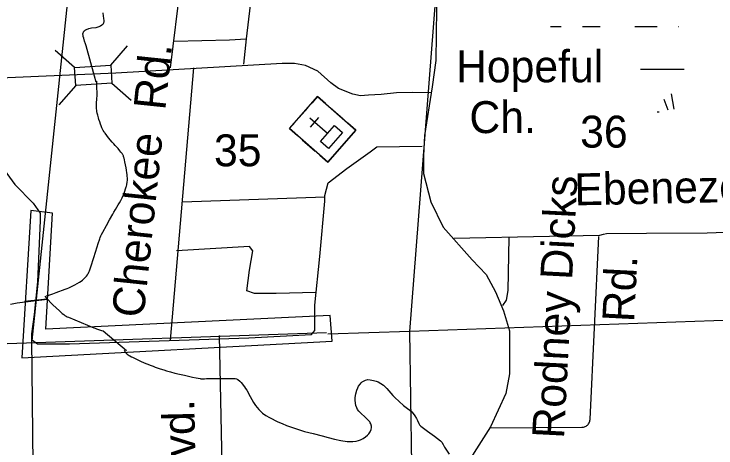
# Model space of a CAD drawing. Extents: x 2480962 to 2688785, y 277103 to 599240.
# Drawn here: x 2571170 to 2581065, y 400443 to 406560 of the extents above; entities that cross this region are included whole.
import ezdxf

# ---------------------------------------------------------------- set-up
doc = ezdxf.new("R2010")
doc.units = 0
for name, color, linetype in [('County Routes Highway Center Lines', 7, 'Continuous'), ('Culture', 7, 'Continuous'), ('Culture Text', 7, 'Continuous'), ('Level 31', 7, 'Continuous'), ('Local Roads Improved', 7, 'Continuous'), ('Local Roads Paved', 7, 'Continuous'), ('Local Roads Related Text', 7, 'Continuous'), ('Narrow River Creek and Branch and Slough', 7, 'Continuous'), ('Section Lines', 7, 'Continuous'), ('Section Numbers', 7, 'Continuous'), ('Swamps', 7, 'Continuous'), ('Township and Range lines', 7, 'Continuous'), ('Uninventoried Roads and Features', 7, 'Continuous')]:
    doc.layers.add(name, color=color, linetype=linetype)

msp = doc.modelspace()

# ---------------------------------------------------------------- linework, layer by layer
at = {"layer": 'County Routes Highway Center Lines'}
msp.add_lwpolyline([(2576923.812, 414892.369), (2576993.261, 413051.984), (2577140.839, 409527.474), (2577158.201, 408260.039), (2577132.158, 407009.966), (2577114.796, 405907.471), (2577062.709, 405534.186), (2576958.537, 404848.382), (2576941.175, 404561.907), (2576941.175, 404310.156), (2577045.347, 403910.828), (2577218.968, 403554.904), (2577626.978, 403094.808), (2577826.643, 402886.463), (2577956.859, 402643.393), (2578069.712, 402374.28), (2578156.523, 402096.486), (2578156.523, 401888.141), (2578156.523, 401488.812), (2578104.437, 401211.018), (2577887.41, 400742.241), (2577435.995, 400030.394)], dxfattribs=at)
at = {"layer": 'Culture'}
for p, q in [((2575447.967, 405396.199), (2575368.975, 405305.864)), ((2575560.884, 405297.46), (2575447.967, 405396.199)), ((2575191.244, 405102.612), (2575309.732, 405238.114)), ((2575809.304, 405080.233), (2575628.635, 405238.216)), ((2575132, 405034.861), (2575053.009, 404944.527)), ((2575589.241, 404874.145), (2575341.166, 405091.071)), ((2575349.329, 404964.377), (2575467.816, 405099.879)), ((2575053.009, 404944.527), (2575165.926, 404845.788)), ((2575989.973, 404922.249), (2575877.055, 405020.989)), ((2575595.015, 404470.577), (2575989.973, 404922.249)), ((2575233.677, 404786.544), (2575414.346, 404628.561)), ((2575482.097, 404569.317), (2575595.015, 404470.577))]:
    msp.add_line(p, q, dxfattribs=at)
for points in [[(2575053.009, 404944.527), (2575447.967, 405396.199), (2575989.973, 404922.249), (2575595.015, 404470.577)], [(2575490.502, 404761.227), (2575687.981, 404987.063), (2575800.899, 404888.323), (2575603.42, 404662.487)]]:
    msp.add_lwpolyline(points, close=True, dxfattribs=at)
at = {"layer": 'Level 31'}
msp.add_lwpolyline([(2571404.517, 403792.853), (2571278.389, 401715.066), (2575653.028, 401947.407), (2575626.475, 402312.513), (2571616.943, 402120.002), (2571709.879, 403753.024)], close=True, dxfattribs=at)
at = {"layer": 'Local Roads Improved'}
for p, q in [((2572532.173, 405841.744), (2572770.214, 406114.523)), ((2572021.353, 405807.006), (2571748.574, 406045.047)), ((2572038.722, 405551.596), (2571800.681, 405278.817)), ((2572549.542, 405586.334), (2572822.321, 405348.293)), ((2579291.39, 400847.78), (2579414.903, 403425.185)), ((2577883.194, 400725.323), (2579174.318, 400734.369))]:
    msp.add_line(p, q, dxfattribs=at)
msp.add_lwpolyline([(2572021.353, 405807.006), (2572532.173, 405841.744), (2572549.542, 405586.334), (2572038.722, 405551.596)], close=True, dxfattribs=at)
for points in [[(2578145.992, 403410.98), (2578129.875, 402661.566), (2578105.701, 402524.576), (2578057.351, 402452.052)], [(2579174.318, 400734.369), (2579186.757, 400735.22), (2579199.038, 400737.368), (2579211.028, 400740.787), (2579222.595, 400745.44), (2579233.612, 400751.278), (2579243.958, 400758.235), (2579253.521, 400766.235), (2579262.195, 400775.192), (2579269.884, 400785.005), (2579276.507, 400795.569), (2579281.989, 400806.768), (2579286.27, 400818.477), (2579289.304, 400830.57), (2579291.057, 400842.914), (2579291.39, 400847.78)]]:
    msp.add_lwpolyline(points, dxfattribs=at)
at = {"layer": 'Local Roads Paved'}
for p, q in [((2573376.092, 401960.683), (2573703.382, 405803.546)), ((2575552.558, 403979.058), (2573544.335, 403908.18)), ((2574061.238, 402028.818), (2574175.504, 396746.483))]:
    msp.add_line(p, q, dxfattribs=at)
for points in [[(2574502.702, 408403.069), (2574523.47, 408119.878), (2574523.47, 407330.09), (2574497.144, 406685.096), (2574444.491, 406211.223), (2574405.002, 405855.818)], [(2573374.423, 405800.724), (2573520.709, 406991.392), (2573578.527, 407488.13), (2573602.05, 407685.495), (2573681.029, 407830.289), (2573996.945, 408027.736), (2574286.534, 408185.694), (2574520.003, 408183.922)], [(2573426.204, 406176.29), (2574207.555, 406198.06), (2574444.491, 406211.223)], [(2577052.818, 405449.786), (2576781.118, 405455.692), (2576562.576, 405449.786), (2576344.034, 405426.16), (2576166.838, 405414.347), (2576054.613, 405408.44), (2575948.296, 405432.066), (2575741.567, 405508.851), (2575635.249, 405591.543), (2575452.147, 405756.926), (2575280.857, 405833.711), (2575121.381, 405863.243), (2574950.091, 405863.243), (2572605.196, 405727.393), (2570750.543, 405644.702), (2570431.59, 405632.888), (2570257.03, 405632.888)], [(2570992.711, 404416.142), (2571181.72, 404156.254), (2571441.608, 403896.366), (2571536.112, 403754.61), (2571536.112, 403648.292), (2571500.673, 402785.937), (2571453.421, 402325.228), (2571417.982, 402053.527), (2571417.982, 401970.835), (2571500.673, 401911.77), (2571949.57, 401911.77), (2574477.568, 401994.461), (2575363.549, 402041.714), (2575410.801, 402100.779), (2575410.801, 402455.171), (2575481.679, 403140.33), (2575552.558, 403919.993), (2575552.558, 404002.684), (2575599.81, 404179.88), (2575859.698, 404380.703), (2576190.464, 404616.964), (2576284.968, 404687.842), (2576922.874, 404699.656)], [(2577370.437, 403400.087), (2578718.518, 403429.805), (2579426.327, 403440.611), (2579477.657, 403456.82), (2579523.584, 403467.627), (2580085.509, 403470.328), (2580941.905, 403475.731), (2581320.124, 403491.941)], [(2575422.614, 402632.367), (2574867.399, 402620.554), (2574560.259, 402620.554), (2574453.942, 402655.994), (2574489.381, 402951.321), (2574536.633, 403223.021), (2574489.381, 403282.087), (2573461.644, 403223.021)]]:
    msp.add_lwpolyline(points, dxfattribs=at)
at = {"layer": 'Narrow River Creek and Branch and Slough'}
for points in [[(2572328.315, 405600.184), (2572305.558, 405682.365), (2572185.245, 406111.298), (2572175.482, 406138.407), (2572163.356, 406179.969), (2572152.272, 406221.719), (2572146.237, 406243.925), (2572142.692, 406261.11), (2572141.48, 406274.046), (2572141.761, 406283.67), (2572144.659, 406297.821), (2572147.438, 406304.708), (2572151.236, 406311.432), (2572158.286, 406320.468), (2572165.243, 406327.017), (2572178.831, 406336.06), (2572189.886, 406341.372), (2572224.699, 406354.587), (2572244.695, 406361.05), (2572262.556, 406364.747), (2572326.175, 406372.688), (2572341.981, 406375.637), (2572353.72, 406378.636), (2572371.07, 406384.83), (2572388.019, 406393.599), (2572407.632, 406407.328), (2572420.772, 406419.375), (2572428.982, 406429.29), (2572433.891, 406437.179), (2572436.734, 406443.331), (2572439.45, 406452.908), (2572440.048, 406462.871), (2572436.673, 406502.38), (2572432.787, 406532.096), (2572425.438, 406576.635)], [(2572473.33, 403581.492), (2572517.314, 403661.218), (2572561.298, 403740.945), (2572575.001, 403765.177), (2572599.891, 403807.015), (2572638.098, 403869.3), (2572656.972, 403900.651), (2572675.312, 403932.397), (2572685.735, 403951.986), (2572694.131, 403969.384), (2572701.001, 403984.793), (2572712.154, 404012.156), (2572719.963, 404032.984), (2572731.137, 404064.679), (2572742.09, 404096.86), (2572746.84, 404111.304), (2572750.718, 404123.97), (2572753.865, 404135.073), (2572758.736, 404154.55), (2572761.784, 404169.195), (2572763.687, 404180.197), (2572765.867, 404196.729), (2572767.16, 404213.294), (2572767.717, 404246.079), (2572766.601, 404274.847), (2572764.549, 404300.066), (2572762.029, 404322.159), (2572756.246, 404360.852), (2572750.986, 404389.876), (2572742.052, 404433.369), (2572732.419, 404476.755), (2572726.129, 404507.1), (2572721.157, 404529.76), (2572718.999, 404538.13), (2572714.608, 404552.506), (2572710.653, 404562.996), (2572707.235, 404570.663), (2572704.381, 404576.284), (2572699.584, 404584.488), (2572694.103, 404592.387), (2572677.39, 404613.763), (2572662.401, 404631.914), (2572635.602, 404662.792), (2572594.89, 404708.166), (2572574.704, 404730.988), (2572554.877, 404754.245), (2572503.392, 404816.213), (2572477.995, 404847.584), (2572453.053, 404879.628), (2572445.177, 404890.449), (2572438.213, 404900.814), (2572426.168, 404920.783), (2572416.608, 404938.775), (2572408.906, 404954.872), (2572396.696, 404983.728), (2572388.405, 405005.848), (2572376.977, 405039.605), (2572366.283, 405073.817), (2572359.662, 405096.025), (2572354.218, 405115.466), (2572349.794, 405132.494), (2572342.987, 405162.355), (2572338.82, 405184.828), (2572336.309, 405201.739), (2572333.661, 405227.213), (2572332.89, 405240.007), (2572332.518, 405252.843), (2572332.72, 405276.604), (2572333.581, 405297.394), (2572338.739, 405370.163), (2572340.711, 405406.555), (2572341.088, 405424.755), (2572340.887, 405442.958), (2572338.372, 405528.756), (2572335.856, 405614.553)], [(2571625.963, 402588.51), (2571659.763, 402598.656), (2571718.328, 402617.938), (2571761.901, 402633.38), (2571892.029, 402682.151), (2571917.929, 402692.202), (2571940.312, 402701.39), (2571978.926, 402718.492), (2572007.486, 402732.285), (2572028.715, 402743.241), (2572060.305, 402760.753), (2572091.655, 402779.681), (2572114.483, 402795), (2572133.685, 402809.54), (2572149.746, 402823.122), (2572163.132, 402835.654), (2572174.266, 402847.113), (2572183.52, 402857.511), (2572191.214, 402866.893), (2572203.697, 402883.942), (2572212.172, 402897.249), (2572217.992, 402907.52), (2572225.804, 402923.387), (2572232.444, 402939.803), (2572256.616, 403008.494), (2572291.067, 403111.779), (2572324.354, 403215.424), (2572339.128, 403264.599), (2572360.543, 403338.572), (2572372.262, 403375.252), (2572378.647, 403393.436), (2572385.484, 403411.484), (2572394.75, 403433.588), (2572403.523, 403452.597), (2572420.043, 403485.286), (2572473.33, 403581.492)], [(2571605.911, 402581.454), (2571629.218, 402553.648), (2571650.133, 402529.91), (2571687.842, 402489.537), (2571716.995, 402460.084), (2571762.019, 402416.951), (2571808.462, 402374.708), (2571838.046, 402348.767), (2571849.347, 402339.309), (2571869.554, 402323.453), (2571885.169, 402312.354), (2571897.194, 402304.595), (2571906.414, 402299.145), (2571920.601, 402291.638), (2571935.262, 402285.026), (2572025.087, 402248.117), (2572114.914, 402211.209), (2572204.74, 402174.299), (2572294.566, 402137.391), (2572313.428, 402130.052), (2572330.109, 402124.134), (2572359.58, 402114.557), (2572404.084, 402100.892), (2572426.289, 402093.822), (2572753.747, 401814.623)], [(2571121.784, 402468.307), (2571214.727, 402487.046), (2571635.089, 402540.142), (2571316.583, 402507.795), (2571325.488, 402509.825)], [(2572720.868, 401818.18), (2572729.457, 401806.249), (2572733.827, 401800.324), (2572738.356, 401794.468), (2572745.508, 401786.061), (2572752.622, 401778.63), (2572759.624, 401772.032), (2572766.458, 401766.149), (2572779.903, 401755.838), (2572792.255, 401747.5), (2572803.435, 401740.654), (2572823.651, 401729.504), (2572839.191, 401721.675), (2572886.292, 401699.517), (2572954.178, 401667.918), (2573005.192, 401645.006), (2573043.653, 401628.466), (2573101.89, 401604.997), (2573131.336, 401593.981), (2573161.053, 401583.515), (2573229.253, 401560.417), (2573280.483, 401543.583), (2573319.028, 401531.46), (2573377.162, 401514.422), (2573435.826, 401499.188), (2573504.464, 401483.157), (2573573.215, 401467.583), (2573683.552, 401441.971), (2573738.997, 401430.135), (2573766.962, 401424.866), (2573795.155, 401420.184), (2573802.454, 401419.231), (2573809.299, 401418.621), (2573822.138, 401418.118), (2573833.375, 401418.246), (2573853.044, 401419.364), (2573882.557, 401421.923), (2573897.312, 401423.002), (2573912.065, 401423.581)], [(2573912.065, 401423.581), (2574267.611, 401423.453), (2574287.749, 401421.043), (2574307.764, 401415.167), (2574326.025, 401406.16), (2574353.761, 401385.597), (2574371.815, 401367.116), (2574418.702, 401304.361), (2574435.031, 401280.844), (2574450.394, 401256.863), (2574497.726, 401169.837), (2574545.456, 401082.698), (2574572.447, 401041.992), (2574618.469, 400985.339), (2574644.306, 400959.29), (2574672.236, 400934.944), (2574720.938, 400900.557), (2574772.621, 400871.644), (2574890.108, 400812.943), (2574949.642, 400785.719), (2575010.392, 400760.902), (2575136.24, 400715.367), (2575264.025, 400676.565), (2575388.213, 400644.889), (2575512.382, 400613.342), (2575599.515, 400589.692), (2575686.758, 400565.917), (2575776.177, 400547.255), (2575866.425, 400534.335), (2575897.95, 400531.836), (2575945.635, 400533.393), (2575993.259, 400539.679), (2576028.124, 400547.678), (2576053.137, 400556.333), (2576089.52, 400574.003), (2576125.396, 400597.818), (2576152.452, 400621.074), (2576169.751, 400640.025), (2576190.541, 400670.609), (2576204.703, 400703.443), (2576209.064, 400729.771), (2576207.994, 400750.872), (2576199.671, 400781.976), (2576192.582, 400796.244), (2576183.602, 400809.018), (2576147.393, 400849.651), (2576109.645, 400888.168), (2576069.893, 400924.152), (2576030.401, 400962.036), (2576012.026, 400987.059), (2576001.544, 401007.546), (2575990.185, 401039.922), (2575982.879, 401072.876), (2575978.773, 401118.469), (2575980.256, 401153.325), (2575988.894, 401205.855), (2576004.082, 401257.661), (2576016.345, 401289.959), (2576027.025, 401312.586), (2576047.993, 401344.318), (2576061.681, 401359.324), (2576078.109, 401373.842), (2576105.416, 401391.483), (2576126.404, 401400.159), (2576158.054, 401406.485), (2576189.097, 401405.574), (2576237.948, 401396.269), (2576274.757, 401385.374), (2576302.034, 401374.616), (2576341.778, 401353.749), (2576379.317, 401326.483), (2576423.585, 401283.401), (2576479.77, 401216.39), (2576507.562, 401183.588), (2576537.795, 401152.349), (2576598.051, 401096.425), (2576659.303, 401041.548), (2576717.96, 400997.627), (2576747.635, 400975.971), (2576775.534, 400951.86), (2576795.17, 400929.94), (2576820.545, 400894.003), (2576844.2, 400856.87), (2576858.088, 400829.74), (2576875.83, 400786.94), (2576887.099, 400767.549), (2576902.295, 400751.314), (2576999.479, 400679.068), (2577097.776, 400608.876), (2577140.438, 400577.856), (2577182.309, 400545.568), (2577200.126, 400525.986), (2577220.255, 400491.005), (2577240.408, 400455.851), (2577304.162, 400356.351)]]:
    msp.add_lwpolyline(points, dxfattribs=at)
at = {"layer": 'Section Lines'}
for p, q in [((2576751.859, 402083.823), (2577178.819, 407641.308)), ((2571948.614, 407004.035), (2571421.858, 401956.76)), ((2571828.156, 405849.826), (2571827.686, 405845.327)), ((2576958.259, 387499.506), (2576751.859, 402083.823)), ((2571417.523, 401976.75), (2571476.359, 396598.182))]:
    msp.add_line(p, q, dxfattribs=at)
at = {"layer": 'Swamps'}
for points in [[(2578731.404, 406382.76), (2578884.693, 406382.764)], [(2579184.693, 406382.771), (2579431.761, 406382.777)], [(2579920.261, 406382.789), (2580234.691, 406382.797)], [(2580534.691, 406382.804), (2580538.025, 406382.805)], [(2579999.803, 405782.786), (2580614.978, 405782.801)], [(2580478.185, 405221.539), (2580438.96, 405437.257)], [(2580391.444, 405205.791), (2580334.668, 405354.827)], [(2580234.707, 405182.786), (2580264.73, 405182.786)]]:
    msp.add_lwpolyline(points, dxfattribs=at)
at = {"layer": 'Township and Range lines'}
for p, q in [((2582058.45, 402269.854), (2576751.859, 402083.823)), ((2575576.213, 402065.11), (2566061.096, 401735.538)), ((2576751.859, 402083.823), (2575591.172, 402048.409))]:
    msp.add_line(p, q, dxfattribs=at)

# ---------------------------------------------------------------- texts
at = {"layer": 'Culture Text'}
for s, rotation, p in [('Hopeful', 0.0669778, (2577401.377, 405596.736)), ('Ch.', 0.0669833, (2577589.568, 404881.544))]:
    msp.add_text(s, height=450, rotation=rotation, dxfattribs=at).set_placement(p)
at = {"layer": 'Local Roads Related Text'}
for s, rotation, p in [('Ebenezer', 1.234675, (2579074.443, 403862.213)), ('Feagle  Blvd.', 91.3051222, (2573788.599, 397619.56))]:
    msp.add_text(s, height=450, rotation=rotation, dxfattribs=at).set_placement(p)
at = {"layer": 'Section Numbers'}
for s, rotation, p in [('36', 0.0293472, (2579151.039, 404677.214)), ('35', 0.02935, (2573989.22, 404414.048))]:
    msp.add_text(s, height=450, rotation=rotation, dxfattribs=at).set_placement(p)
at = {"layer": 'Uninventoried Roads and Features'}
for s, rotation, p in [('Cherokee  Rd.', 84.0419028, (2572995.464, 402267.219)), ('Rodney Dicks', 87.0531694, (2578922.054, 400567.939)), ('Rd.', 87.0531722, (2579910.966, 402209.924))]:
    msp.add_text(s, height=450, rotation=rotation, dxfattribs=at).set_placement(p)

doc.saveas('drawing.dxf')
